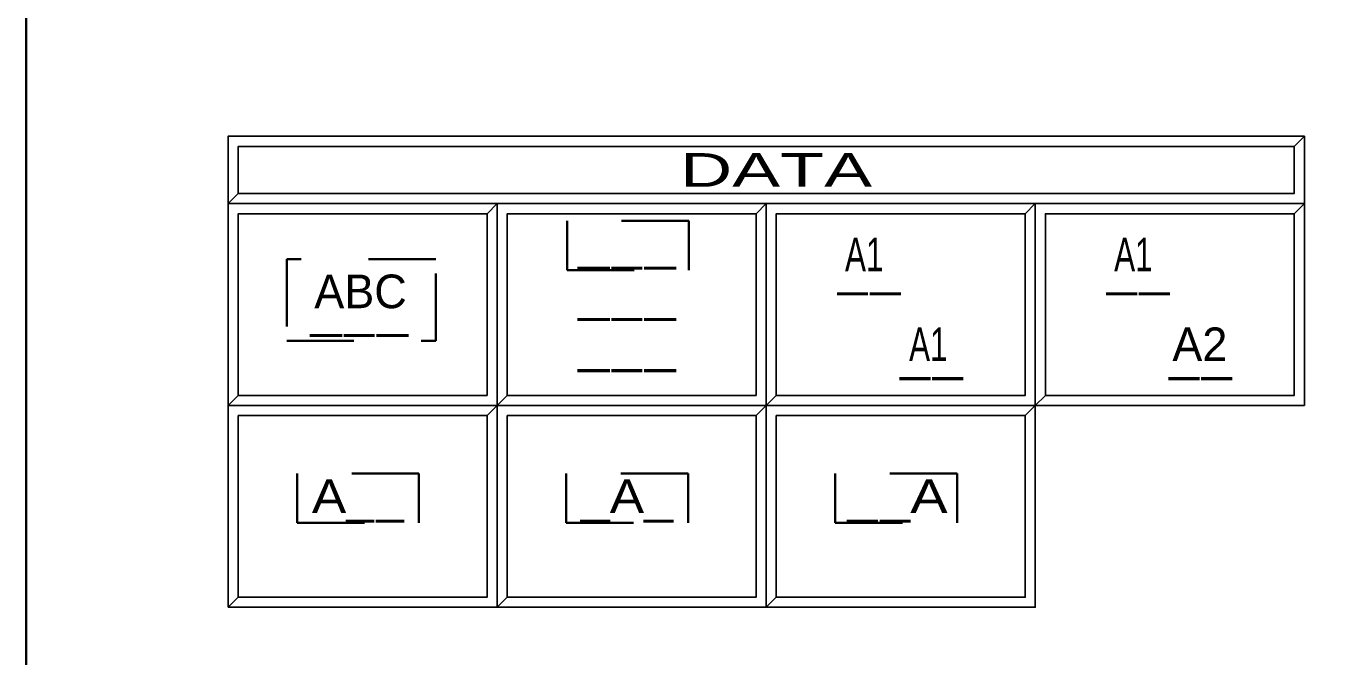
# Model space of a CAD drawing. Extents: x 95906.8 to 95923.6, y 90964.8 to 90972.8.
# Drawn here: x 95906.832 to 95908.785, y 90968.688 to 90969.625 of the extents above; entities that cross this region are included whole.
import ezdxf
from ezdxf.enums import TextEntityAlignment as Align

# ---------------------------------------------------------------- set-up
doc = ezdxf.new("R2010")
doc.units = 0
doc.header["$LTSCALE"] = 0.019
doc.linetypes.add('MEDIUM_DASHED', pattern=[4.5, 3, -1.5])
for name, color, linetype, lineweight in [('1', 7, 'Continuous', 25), ('11', 7, 'Continuous', 25), ('12', 7, 'Continuous', 25), ('18', 7, 'Continuous', 25), ('2', 7, 'Continuous', 13), ('3', 7, 'Continuous', 25), ('6', 7, 'Continuous', 35), ('7', 7, 'Continuous', 35)]:
    doc.layers.add(name, color=color, linetype=linetype, lineweight=lineweight)

msp = doc.modelspace()

# ---------------------------------------------------------------- linework, layer by layer
at = {"layer": '1'}
for points in [[(95907.1323, 90969.3617), (95908.7323, 90969.3617), (95908.7323, 90969.4617), (95907.1323, 90969.4617)], [(95907.1323, 90969.0617), (95907.5323, 90969.0617), (95907.5323, 90969.3617), (95907.1323, 90969.3617)], [(95907.5323, 90969.0617), (95907.9323, 90969.0617), (95907.9323, 90969.3617), (95907.5323, 90969.3617)], [(95907.9323, 90969.0617), (95908.3323, 90969.0617), (95908.3323, 90969.3617), (95907.9323, 90969.3617)], [(95908.3323, 90969.0617), (95908.7323, 90969.0617), (95908.7323, 90969.3617), (95908.3323, 90969.3617)], [(95907.1323, 90968.7617), (95907.5323, 90968.7617), (95907.5323, 90969.0617), (95907.1323, 90969.0617)], [(95907.5323, 90968.7617), (95907.9323, 90968.7617), (95907.9323, 90969.0617), (95907.5323, 90969.0617)], [(95907.9323, 90968.7617), (95908.3323, 90968.7617), (95908.3323, 90969.0617), (95907.9323, 90969.0617)]]:
    msp.add_lwpolyline(points, close=True, dxfattribs=at)
at = {"layer": '11'}
for points in [[(95907.5473, 90969.0767), (95907.9173, 90969.0767), (95907.9173, 90969.3467), (95907.5473, 90969.3467)], [(95907.9473, 90969.0767), (95908.3173, 90969.0767), (95908.3173, 90969.3467), (95907.9473, 90969.3467)], [(95908.3473, 90969.0767), (95908.7173, 90969.0767), (95908.7173, 90969.3467), (95908.3473, 90969.3467)], [(95907.1473, 90968.7767), (95907.5173, 90968.7767), (95907.5173, 90969.0467), (95907.1473, 90969.0467)], [(95907.5473, 90968.7767), (95907.9173, 90968.7767), (95907.9173, 90969.0467), (95907.5473, 90969.0467)], [(95907.9473, 90968.7767), (95908.3173, 90968.7767), (95908.3173, 90969.0467), (95907.9473, 90969.0467)]]:
    msp.add_lwpolyline(points, close=True, dxfattribs=at)
at = {"layer": '12'}
msp.add_lwpolyline([(95907.1473, 90969.0767), (95907.5173, 90969.0767), (95907.5173, 90969.3467), (95907.1473, 90969.3467)], close=True, dxfattribs=at)
at = {"layer": '18'}
msp.add_lwpolyline([(95907.1473, 90969.3767), (95908.7173, 90969.3767), (95908.7173, 90969.4467), (95907.1473, 90969.4467)], close=True, dxfattribs=at)
at = {"layer": '2'}
for points in [[(95907.1323, 90969.4617), (95907.1323, 90969.3617), (95907.1473, 90969.3767), (95907.1473, 90969.4467), (95908.7173, 90969.4467), (95908.7323, 90969.4617)], [(95907.1323, 90969.3617), (95907.1323, 90969.0617), (95907.1473, 90969.0767), (95907.1473, 90969.3467), (95907.5173, 90969.3467), (95907.5323, 90969.3617)], [(95907.5323, 90969.3617), (95907.5323, 90969.0617), (95907.5473, 90969.0767), (95907.5473, 90969.3467), (95907.9173, 90969.3467), (95907.9323, 90969.3617)], [(95907.9323, 90969.3617), (95907.9323, 90969.0617), (95907.9473, 90969.0767), (95907.9473, 90969.3467), (95908.3173, 90969.3467), (95908.3323, 90969.3617)], [(95908.3323, 90969.3617), (95908.3323, 90969.0617), (95908.3473, 90969.0767), (95908.3473, 90969.3467), (95908.7173, 90969.3467), (95908.7323, 90969.3617)], [(95907.1323, 90969.0617), (95907.1323, 90968.7617), (95907.1473, 90968.7767), (95907.1473, 90969.0467), (95907.5173, 90969.0467), (95907.5323, 90969.0617)], [(95907.5323, 90969.0617), (95907.5323, 90968.7617), (95907.5473, 90968.7767), (95907.5473, 90969.0467), (95907.9173, 90969.0467), (95907.9323, 90969.0617)], [(95907.9323, 90969.0617), (95907.9323, 90968.7617), (95907.9473, 90968.7767), (95907.9473, 90969.0467), (95908.3173, 90969.0467), (95908.3323, 90969.0617)]]:
    msp.add_lwpolyline(points, close=True, dxfattribs=at)
at = {"layer": '3'}
for points in [[(95907.1323, 90969.3617), (95908.7323, 90969.3617), (95908.7323, 90969.4617), (95908.7173, 90969.4467), (95908.7173, 90969.3767), (95907.1473, 90969.3767)], [(95907.1323, 90969.0617), (95907.5323, 90969.0617), (95907.5323, 90969.3617), (95907.5173, 90969.3467), (95907.5173, 90969.0767), (95907.1473, 90969.0767)], [(95907.5323, 90969.0617), (95907.9323, 90969.0617), (95907.9323, 90969.3617), (95907.9173, 90969.3467), (95907.9173, 90969.0767), (95907.5473, 90969.0767)], [(95907.9323, 90969.0617), (95908.3323, 90969.0617), (95908.3323, 90969.3617), (95908.3173, 90969.3467), (95908.3173, 90969.0767), (95907.9473, 90969.0767)], [(95908.3323, 90969.0617), (95908.7323, 90969.0617), (95908.7323, 90969.3617), (95908.7173, 90969.3467), (95908.7173, 90969.0767), (95908.3473, 90969.0767)], [(95907.1323, 90968.7617), (95907.5323, 90968.7617), (95907.5323, 90969.0617), (95907.5173, 90969.0467), (95907.5173, 90968.7767), (95907.1473, 90968.7767)], [(95907.5323, 90968.7617), (95907.9323, 90968.7617), (95907.9323, 90969.0617), (95907.9173, 90969.0467), (95907.9173, 90968.7767), (95907.5473, 90968.7767)], [(95907.9323, 90968.7617), (95908.3323, 90968.7617), (95908.3323, 90969.0617), (95908.3173, 90969.0467), (95908.3173, 90968.7767), (95907.9473, 90968.7767)]]:
    msp.add_lwpolyline(points, close=True, dxfattribs=at)
at = {"layer": '6', "linetype": 'MEDIUM_DASHED'}
for points in [[(95907.6362, 90969.2625), (95907.8173, 90969.2625), (95907.8173, 90969.3363), (95907.6362, 90969.3363)], [(95907.2194, 90969.1576), (95907.4409, 90969.1576), (95907.4409, 90969.2791), (95907.2194, 90969.2791)], [(95907.235, 90968.887), (95907.4161, 90968.887), (95907.4161, 90968.9608), (95907.235, 90968.9608)], [(95907.635, 90968.887), (95907.8161, 90968.887), (95907.8161, 90968.9608), (95907.635, 90968.9608)], [(95908.035, 90968.887), (95908.2161, 90968.887), (95908.2161, 90968.9608), (95908.035, 90968.9608)]]:
    msp.add_lwpolyline(points, close=True, dxfattribs=at)
at = {"layer": '7'}
msp.add_lwpolyline([(95906.8323, 90972.7617), (95918.8323, 90972.7617), (95918.8323, 90964.7617), (95906.8323, 90964.7617)], close=True, dxfattribs=at)

# ---------------------------------------------------------------- texts
at = {"layer": '6'}
for s, width, p in [('A1', 0.7, (95908.078, 90969.261)), ('A1', 0.7, (95908.4781, 90969.261)), ('___', 1.3, (95907.7253, 90969.2779)), ('__', 1.25, (95908.085, 90969.2398)), ('__', 1.25, (95908.485, 90969.2398)), ('___', 1.3, (95907.7253, 90969.2017)), ('___', 1.3, (95907.3274, 90969.1779)), ('A1', 0.7, (95908.1733, 90969.1276)), ('___', 1.3, (95907.7253, 90969.1255)), ('__', 1.25, (95908.1779, 90969.1136)), ('__', 1.25, (95908.5779, 90969.1136)), ('A__', 1.15, (95907.3252, 90968.9017)), ('_A_', 1.15, (95907.7252, 90968.9017)), ('__A', 1.25, (95908.1277, 90968.9017))]:
    msp.add_text(s, height=0.04999, dxfattribs=dict(at, width=width)).set_placement(p, align=Align.CENTER)
for s, p in [('ABC', (95907.3292, 90969.2062)), ('A2', (95908.5769, 90969.1276))]:
    msp.add_text(s, height=0.04999, dxfattribs=at).set_placement(p, align=Align.CENTER)
at = {"layer": '7', "width": 1.6}
msp.add_text('          DATA         ', height=0.04999, dxfattribs=at).set_placement((95907.9322, 90969.3867), align=Align.CENTER)

doc.saveas('drawing.dxf')
